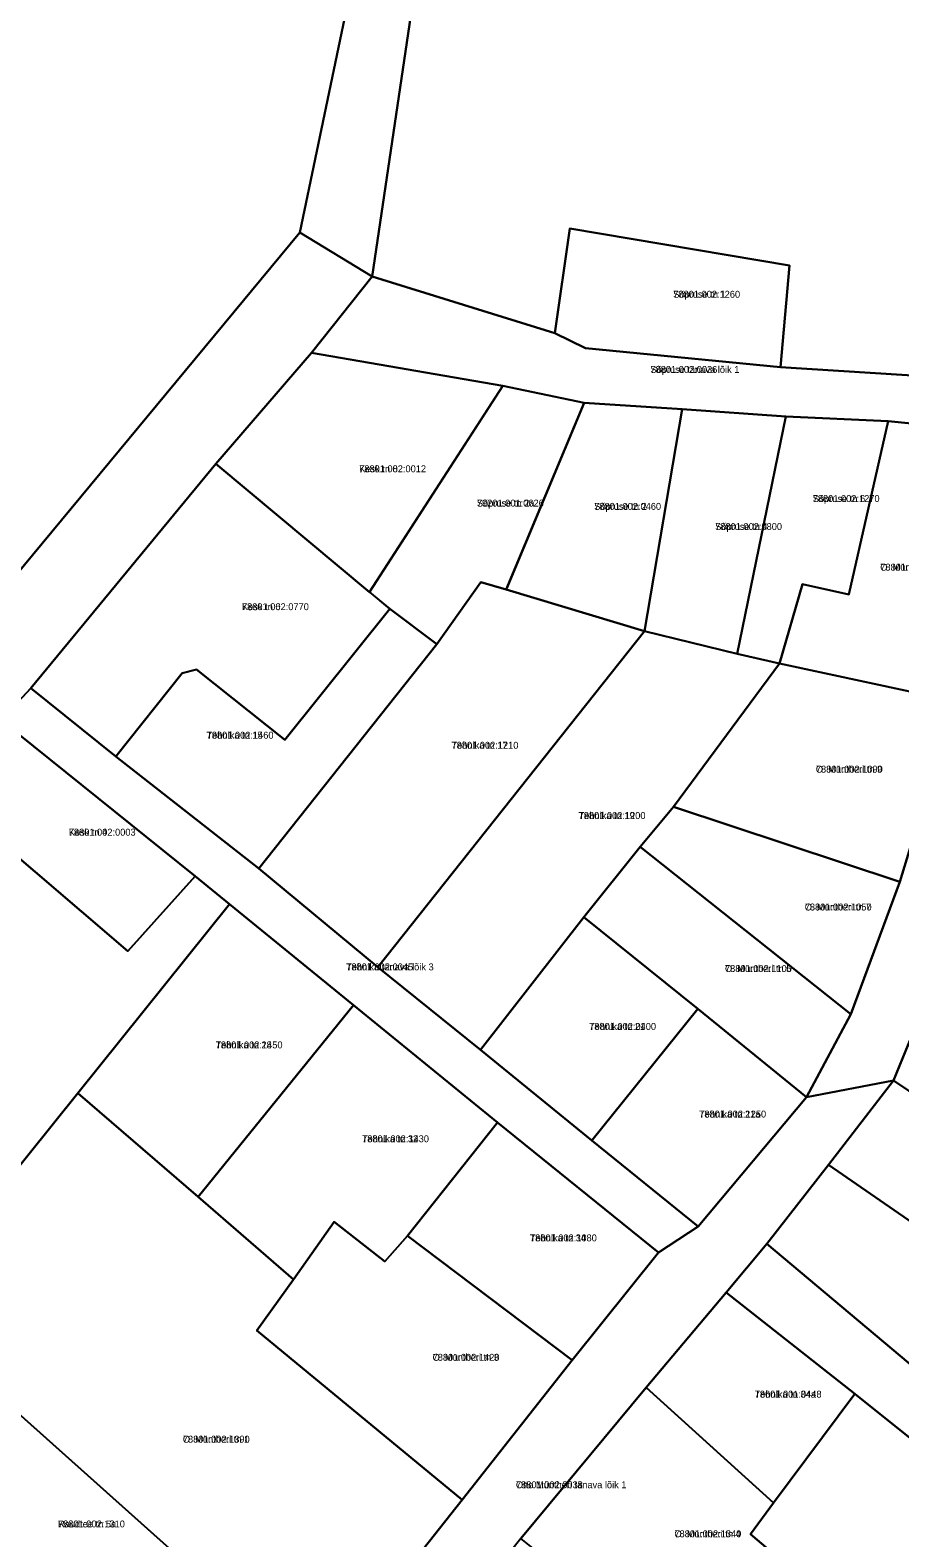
# Model space of a CAD drawing. Extents: x 587616 to 632239, y 6547421 to 6574977.
# Drawn here: x 620871.7 to 621060.2, y 6559884 to 6560210.9 of the extents above; entities that cross this region are included whole.
import ezdxf

# ---------------------------------------------------------------- set-up
doc = ezdxf.new("R2010")
doc.units = 0
for name, color, linetype in [('L_AADRESS', 7, 'Continuous'), ('PIIR', 7, 'Continuous'), ('TUNNUS', 7, 'Continuous')]:
    doc.layers.add(name, color=color, linetype=linetype)

msp = doc.modelspace()

# ---------------------------------------------------------------- linework, layer by layer
at = {"layer": 'PIIR'}
for points in [[(620732.17, 6560274.08), (620735.99, 6560273.96), (620764.49, 6560295.17), (620798.19, 6560320.26), (620815.64, 6560333.08), (620841.33, 6560300.64), (620855.78, 6560309.67), (620865.57, 6560320.52), (620869.51, 6560315.76), (620905.55, 6560272.24), (620926.58, 6560289.63), (620947.56, 6560260.25), (620948.55, 6560255.26), (620930.14, 6560166.98), (620859.9, 6560082.32), (620698.2, 6560244.19)], [(621099, 6560234.38), (621174.53, 6560233.59), (621199.74, 6560219.21), (621206.93, 6560208.72), (621203.52, 6560152.25), (621188, 6560129.02), (621172.9, 6560123.58), (621114.75, 6560133.46), (621067.51, 6560135.74), (621034.33, 6560137.84), (621036.27, 6560159.86), (620988.65, 6560167.89), (620985.4, 6560145.2), (620945.8, 6560157.47), (620961.14, 6560260.98)], [(620930.14, 6560166.98), (620945.8, 6560157.47), (620932.68, 6560140.9), (620911.9, 6560116.84), (620871.81, 6560068.2), (620865.37, 6560061.29), (620852.59, 6560045.63), (620763.54, 6559936.6), (620750.39, 6559923.57), (620738.59, 6559932.59), (620764.74, 6559964.86), (620790.31, 6559996.35), (620799.68, 6560004.05), (620815.81, 6560023.02), (620837.4, 6560048.53), (620853.77, 6560068.02), (620859.9, 6560082.32)], [(620985.4, 6560145.2), (620988.65, 6560167.89), (621036.27, 6560159.86), (621034.33, 6560137.84), (620992.08, 6560141.9)], [(620945.8, 6560157.47), (620985.4, 6560145.2), (620992.08, 6560141.9), (621034.33, 6560137.84), (621067.51, 6560135.74), (621114.75, 6560133.46), (621172.9, 6560123.58), (621176.13, 6560115.67), (621159.05, 6560117.13), (621153.89, 6560118.03), (621123.01, 6560120.12), (621091.51, 6560123.67), (621077.81, 6560124.05), (621057.68, 6560126.07), (621035.52, 6560127.15), (621013.05, 6560128.71), (620991.77, 6560130.07), (620974.11, 6560133.78), (620932.68, 6560140.9)], [(620911.9, 6560116.84), (620932.68, 6560140.9), (620974.11, 6560133.78), (620945.25, 6560089.06)], [(620974.86, 6560089.62), (620969.34, 6560091.23), (620959.82, 6560077.73), (620949.64, 6560085.41), (620945.26, 6560089.08), (620974.11, 6560133.78), (620991.77, 6560130.07), (620974.98, 6560089.92)], [(620974.86, 6560089.62), (620991.77, 6560130.07), (621013.05, 6560128.71), (621004.82, 6560080.54)], [(621013.05, 6560128.71), (621035.52, 6560127.15), (621024.95, 6560075.65), (621004.82, 6560080.54)], [(621034.11, 6560073.56), (621024.95, 6560075.65), (621035.52, 6560127.15), (621057.68, 6560126.07), (621049.17, 6560088.56), (621039.13, 6560090.76)], [(621057.68, 6560126.07), (621077.81, 6560124.05), (621072.11, 6560065.43), (621034.11, 6560073.56), (621039.13, 6560090.76), (621049.17, 6560088.56)], [(621077.81, 6560124.05), (621091.51, 6560123.67), (621087.79, 6560090.75), (621084.17, 6560060.9), (621080.61, 6560048.81), (621068.61, 6560007.04), (621058.86, 6559983.15), (621039.98, 6559979.54), (621049.6, 6559997.55), (621060.19, 6560026.25), (621072.11, 6560065.43)], [(620871.81, 6560068.2), (620911.9, 6560116.84), (620945.25, 6560089.06), (620949.64, 6560085.41), (620926.91, 6560056.99), (620907.73, 6560072.28), (620904.61, 6560071.44), (620890.22, 6560053.42)], [(620921.23, 6560029.13), (620959.82, 6560077.73), (620969.34, 6560091.23), (620974.86, 6560089.62), (621004.82, 6560080.54), (620947.02, 6560007.74)], [(620890.22, 6560053.42), (620904.61, 6560071.44), (620907.73, 6560072.28), (620926.91, 6560056.99), (620949.64, 6560085.41), (620959.82, 6560077.73), (620921.23, 6560029.13)], [(620947.02, 6560007.74), (621004.82, 6560080.54), (621024.95, 6560075.65), (621034.11, 6560073.56), (621011.12, 6560042.49), (621003.91, 6560033.82), (620991.68, 6560018.54), (620969.28, 6559989.78)], [(621034.11, 6560073.56), (621072.11, 6560065.43), (621060.19, 6560026.25), (621011.12, 6560042.49)], [(620871.81, 6560068.2), (620890.22, 6560053.42), (620921.23, 6560029.13), (620947.02, 6560007.74), (620969.28, 6559989.78), (620993.46, 6559970.17), (621016.5, 6559951.5), (621007.91, 6559945.88), (620972.97, 6559974.05), (620941.74, 6559999.51), (620914.9, 6560021.39), (620907.45, 6560027.44), (620865.37, 6560061.29)], [(620865.37, 6560061.29), (620907.45, 6560027.44), (620892.83, 6560011.18), (620852.59, 6560045.63)], [(620782.92, 6559904.64), (620789.23, 6559912.76), (620776.51, 6559924.57), (620763.54, 6559936.6), (620852.59, 6560045.63), (620892.83, 6560011.18), (620907.45, 6560027.44), (620914.9, 6560021.39), (620882.03, 6559980.44), (620844.18, 6559933.31), (620805.31, 6559884.84)], [(621011.12, 6560042.49), (621060.19, 6560026.25), (621049.6, 6559997.55), (621003.91, 6560033.82)], [(621039.98, 6559979.54), (621016.44, 6559998.73), (620991.68, 6560018.54), (621003.91, 6560033.82), (621049.6, 6559997.55)], [(620882.03, 6559980.44), (620914.9, 6560021.39), (620941.74, 6559999.51), (620908.09, 6559957.91)], [(620969.28, 6559989.78), (620991.68, 6560018.54), (621016.44, 6559998.73), (620993.46, 6559970.17)], [(621098.74, 6559956.25), (621058.86, 6559983.15), (621068.61, 6560007.04), (621110.93, 6559975.13)], [(620928.77, 6559940.03), (620908.09, 6559957.91), (620941.74, 6559999.51), (620972.97, 6559974.05), (620953.48, 6559949.5), (620948.55, 6559943.92), (620937.6, 6559952.53)], [(621016.44, 6559998.73), (621039.98, 6559979.54), (621016.5, 6559951.5), (620993.46, 6559970.17)], [(620897.59, 6559806.56), (620920.58, 6559835.64), (620965.35, 6559892.25), (620989.19, 6559922.5), (621007.91, 6559945.88), (621016.5, 6559951.5), (621039.98, 6559979.54), (621058.86, 6559983.15), (621044.75, 6559964.88), (621031.34, 6559947.77), (621022.58, 6559937.22), (621005.2, 6559916.6), (620978.08, 6559883.89), (620965.5, 6559868.06), (620904.67, 6559792.68), (620895.1, 6559799.23), (620897.96, 6559799.35), (620901.34, 6559803.39)], [(621058.86, 6559983.15), (621098.74, 6559956.25), (621085.34, 6559936.83), (621044.75, 6559964.88)], [(620844.18, 6559933.31), (620882.03, 6559980.44), (620908.09, 6559957.91), (620928.77, 6559940.03), (620920.8, 6559928.93), (620965.35, 6559892.25), (620920.58, 6559835.64), (620888.76, 6559861.52), (620903.28, 6559880.49), (620869.11, 6559911)], [(620972.97, 6559974.05), (621007.91, 6559945.88), (620989.19, 6559922.5), (620953.48, 6559949.5)], [(621069.28, 6559915.85), (621031.34, 6559947.77), (621044.75, 6559964.88), (621085.34, 6559936.83)], [(620928.77, 6559940.03), (620937.6, 6559952.53), (620948.55, 6559943.92), (620953.48, 6559949.5), (620989.19, 6559922.5), (620965.35, 6559892.25), (620920.8, 6559928.93)], [(621031.34, 6559947.77), (621069.28, 6559915.85), (621085.68, 6559902.02), (621102.69, 6559887.65), (621121.84, 6559871.88), (621130.18, 6559862.42), (621119.84, 6559857.1), (621110.44, 6559867.18), (621050.48, 6559915.25), (621022.58, 6559937.22)], [(621005.2, 6559916.6), (621022.58, 6559937.22), (621050.48, 6559915.25), (621032.85, 6559891.57)], [(621005.2, 6559916.6), (621032.85, 6559891.57), (621027.84, 6559884.83), (621044.61, 6559870.56), (621026.13, 6559845.38), (620978.08, 6559883.89)], [(621085.15, 6559836.06), (621044.61, 6559870.56), (621027.84, 6559884.83), (621032.85, 6559891.57), (621050.48, 6559915.25), (621110.44, 6559867.18)], [(620869.11, 6559911), (620903.28, 6559880.49), (620888.76, 6559861.52), (620882.27, 6559866.88), (620851.73, 6559891.89)]]:
    msp.add_lwpolyline(points, close=True, dxfattribs=at)
msp.add_lwpolyline([(620961.14, 6560260.98), (620945.8, 6560157.47), (620930.14, 6560166.98), (620948.55, 6560255.26)], dxfattribs=at)

# ---------------------------------------------------------------- texts
at = {"layer": 'L_AADRESS'}
for s, p in [('Sõpruse tn 1', (621011.08, 6560152.87)), ('Sõpruse tänava lõik 1', (621006.14, 6560136.57)), ('Kesk tn 8', (620943, 6560115.03)), ('Sõpruse tn 2a', (620968.52, 6560107.59)), ('Sõpruse tn 2', (620993.95, 6560106.88)), ('Sõpruse tn 6', (621041.32, 6560108.57)), ('Sõpruse tn 4', (621020.17, 6560102.51)), ('O. Müntheri tn 11', (621055.96, 6560093.69)), ('Kesk tn 6', (620917.59, 6560085.13)), ('Tehnika tn 15', (620909.93, 6560057.27)), ('Tehnika tn 17', (620963.02, 6560055.09)), ('O. Müntheri tn 9', (621042, 6560049.9)), ('Tehnika tn 19', (620990.57, 6560039.85)), ('Kesk tn 4', (620880.04, 6560036.24)), ('O. Müntheri tn 7', (621039.59, 6560020.02)), ('Tehnika tänava lõik 3', (620940.2, 6560007.04)), ('O. Müntheri tn 5', (621022.3, 6560006.68)), ('Tehnika tn 21', (620992.86, 6559994.13)), ('Tehnika tn 28', (620911.89, 6559990.12)), ('Tehnika tn 21a', (621016.72, 6559975.13)), ('Tehnika tn 32', (620943.63, 6559969.77)), ('Tehnika tn 34', (620980.02, 6559948.28)), ('O. Müntheri tn 3', (620958.92, 6559922.39)), ('Tehnika tn 34a', (621028.74, 6559914.4)), ('O. Müntheri tn 1', (620904.77, 6559904.64)), ('Otto Müntheri tänava lõik 1', (620976.98, 6559894.76)), ('Raudtee tn 5a', (620877.71, 6559886.26)), ('O. Müntheri tn 4', (621011.34, 6559884.13))]:
    msp.add_text(s, height=1.5, dxfattribs=at).set_placement(p)
at = {"layer": 'TUNNUS'}
for s, p in [('78801:002:1260', (621011.08, 6560152.87)), ('78801:002:0036', (621006.14, 6560136.57)), ('78801:002:0012', (620943, 6560115.03)), ('79201:001:0626', (620968.52, 6560107.59)), ('78801:002:0460', (620993.95, 6560106.88)), ('78801:002:1270', (621041.32, 6560108.57)), ('78801:002:0800', (621020.17, 6560102.51)), ('78801:002:0008', (621055.96, 6560093.69)), ('78801:002:0770', (620917.59, 6560085.13)), ('78801:002:1460', (620909.93, 6560057.27)), ('78801:002:1210', (620963.02, 6560055.09)), ('78801:002:1090', (621042, 6560049.9)), ('78801:002:1200', (620990.57, 6560039.85)), ('78801:002:0003', (620880.04, 6560036.24)), ('78801:002:1050', (621039.59, 6560020.02)), ('78801:002:0045', (620940.2, 6560007.04)), ('78801:002:1100', (621022.3, 6560006.68)), ('78801:002:0400', (620992.86, 6559994.13)), ('78801:002:1450', (620911.89, 6559990.12)), ('78801:002:1250', (621016.72, 6559975.13)), ('78801:002:1430', (620943.63, 6559969.77)), ('78801:002:1080', (620980.02, 6559948.28)), ('78801:002:1420', (620958.92, 6559922.39)), ('78601:001:0448', (621028.74, 6559914.4)), ('78801:002:1390', (620904.77, 6559904.64)), ('78801:002:0038', (620976.98, 6559894.76)), ('78801:002:1310', (620877.71, 6559886.26)), ('78801:002:1340', (621011.34, 6559884.13))]:
    msp.add_text(s, height=1.5, dxfattribs=at).set_placement(p)

doc.saveas('drawing.dxf')
